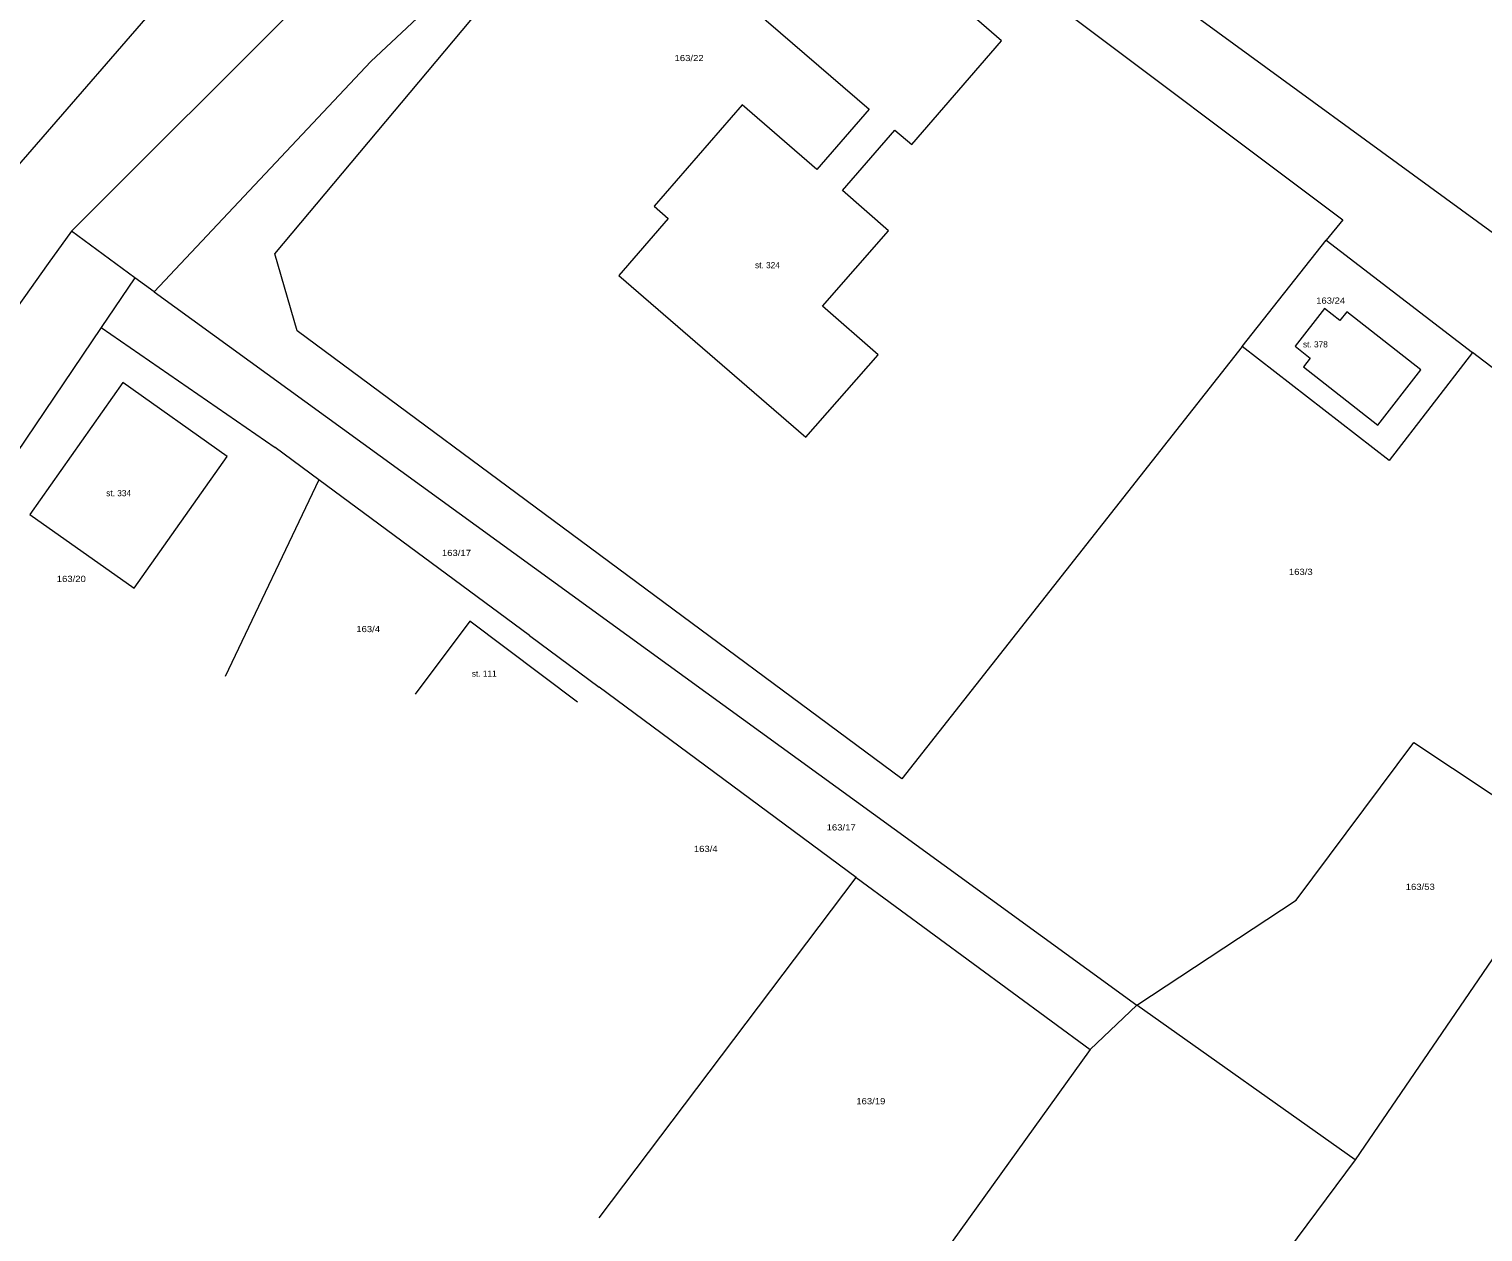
# Model space of a CAD drawing. Extents: x -694702 to -694000, y -1089746 to -1089192.
# Drawn here: x -694548.9 to -694431.2, y -1089654.8 to -1089557.5 of the extents above; entities that cross this region are included whole.
import ezdxf

# ---------------------------------------------------------------- set-up
doc = ezdxf.new("R2010")
doc.units = 0
doc.header["$LTSCALE"] = 0.2
doc.layers.add('50', color=7, linetype='Continuous', lineweight=13)
doc.layers.add('52', color=7, linetype='Continuous', lineweight=13)

msp = doc.modelspace()

# ---------------------------------------------------------------- linework, layer by layer
at = {"layer": '50'}
for p, q in [((-694487.76, -1089516.16), (-694545.41, -1089573.81)), ((-694430.38, -1089574.01), (-694457.65, -1089554.09)), ((-694540.3, -1089577.6), (-694545.41, -1089573.81)), ((-694450.7, -1089583.15), (-694443.91, -1089574.53)), ((-694443.91, -1089574.53), (-694432.09, -1089583.62)), ((-694538.73, -1089578.73), (-694540.3, -1089577.6)), ((-694543.01, -1089581.61), (-694552.96, -1089596.31)), ((-694409.08, -1089601.31), (-694432.09, -1089583.62)), ((-694525.41, -1089593.93), (-694532.99, -1089609.85)), ((-694508.37, -1089606.54), (-694502.72, -1089610.72)), ((-694481.93, -1089626.11), (-694502.72, -1089610.72)), ((-694424.24, -1089623.56), (-694441.56, -1089648.97)), ((-694502.72, -1089653.66), (-694481.93, -1089626.11)), ((-694481.93, -1089626.11), (-694463, -1089640.04)), ((-694463, -1089640.04), (-694459.23, -1089636.44)), ((-694441.56, -1089648.97), (-694459.23, -1089636.44)), ((-694463, -1089640.04), (-694482.62, -1089667.31)), ((-694441.56, -1089648.97), (-694462.18, -1089676.61))]:
    msp.add_line(p, q, dxfattribs=at)
for points in [[(-694496.69, -1089537.12), (-694521.2, -1089560.09), (-694538.73, -1089578.73)], [(-694450.7, -1089583.15), (-694478.25, -1089618.12), (-694527.15, -1089581.87), (-694528.98, -1089575.65), (-694496.69, -1089537.12)], [(-694496.69, -1089537.12), (-694491.16, -1089536.39), (-694442.58, -1089572.9), (-694443.91, -1089574.53)], [(-694563.76, -1089588.86), (-694559.06, -1089579.24), (-694538.16, -1089555.18)], [(-694545.41, -1089573.81), (-694547.31, -1089576.44), (-694555.66, -1089588.18), (-694558.98, -1089596.45), (-694560.19, -1089606.54)], [(-694540.3, -1089577.6), (-694543.01, -1089581.61), (-694528.95, -1089591.31)], [(-694538.73, -1089578.73), (-694478.86, -1089622.17), (-694459.23, -1089636.44)], [(-694432.09, -1089583.62), (-694438.81, -1089592.36), (-694450.7, -1089583.15)], [(-694508.37, -1089606.54), (-694525.41, -1089593.93), (-694528.95, -1089591.31)], [(-694504.49, -1089611.93), (-694513.19, -1089605.38), (-694517.62, -1089611.29)], [(-694459.23, -1089636.44), (-694446.33, -1089627.94), (-694436.83, -1089615.18), (-694424.24, -1089623.56)]]:
    msp.add_lwpolyline(points, dxfattribs=at)
for points in [[(-694501.13, -1089577.39), (-694486.01, -1089590.48), (-694480.16, -1089583.83), (-694484.67, -1089579.87), (-694479.32, -1089573.79), (-694483.04, -1089570.52), (-694478.8, -1089565.63), (-694477.44, -1089566.81), (-694470.17, -1089558.42), (-694484.16, -1089546.26), (-694486.96, -1089549.32), (-694488.49, -1089547.96), (-694487.63, -1089546.99), (-694492.48, -1089542.7), (-694499.7, -1089550.91), (-694494.89, -1089555.14), (-694493.3, -1089553.22), (-694480.9, -1089563.95), (-694485.12, -1089568.83), (-694491.17, -1089563.59), (-694498.27, -1089571.8), (-694497.14, -1089572.78)], [(-694439.75, -1089589.5), (-694436.26, -1089585.03), (-694442.25, -1089580.33), (-694442.82, -1089581.04), (-694444.05, -1089580.08), (-694446.42, -1089583.13), (-694445.2, -1089584.09), (-694445.75, -1089584.79)], [(-694541.27, -1089586.06), (-694548.8, -1089596.75), (-694540.36, -1089602.71), (-694532.83, -1089592.04)]]:
    msp.add_lwpolyline(points, close=True, dxfattribs=at)

# ---------------------------------------------------------------- texts
at = {"layer": '52', "width": 1.15}
for s, p in [('163/22', (-694496.63, -1089560.05)), ('163/24', (-694444.73, -1089579.68)), ('163/17', (-694515.45, -1089600.1)), ('163/20', (-694546.61, -1089602.2)), ('163/3', (-694446.93, -1089601.63)), ('163/4', (-694522.38, -1089606.26)), ('163/17', (-694484.33, -1089622.31)), ('163/4', (-694495.07, -1089624.05)), ('163/53', (-694437.48, -1089627.12)), ('163/19', (-694481.93, -1089644.47))]:
    msp.add_text(s, height=0.5, dxfattribs=at).set_placement(p)
at = {"layer": '52'}
for s, p in [('st. 324', (-694490.12, -1089576.81)), ('st. 378', (-694445.79, -1089583.22)), ('st. 334', (-694542.61, -1089595.26)), ('st. 111', (-694513.03, -1089609.87))]:
    msp.add_text(s, height=0.5, dxfattribs=at).set_placement(p)

doc.saveas('drawing.dxf')
